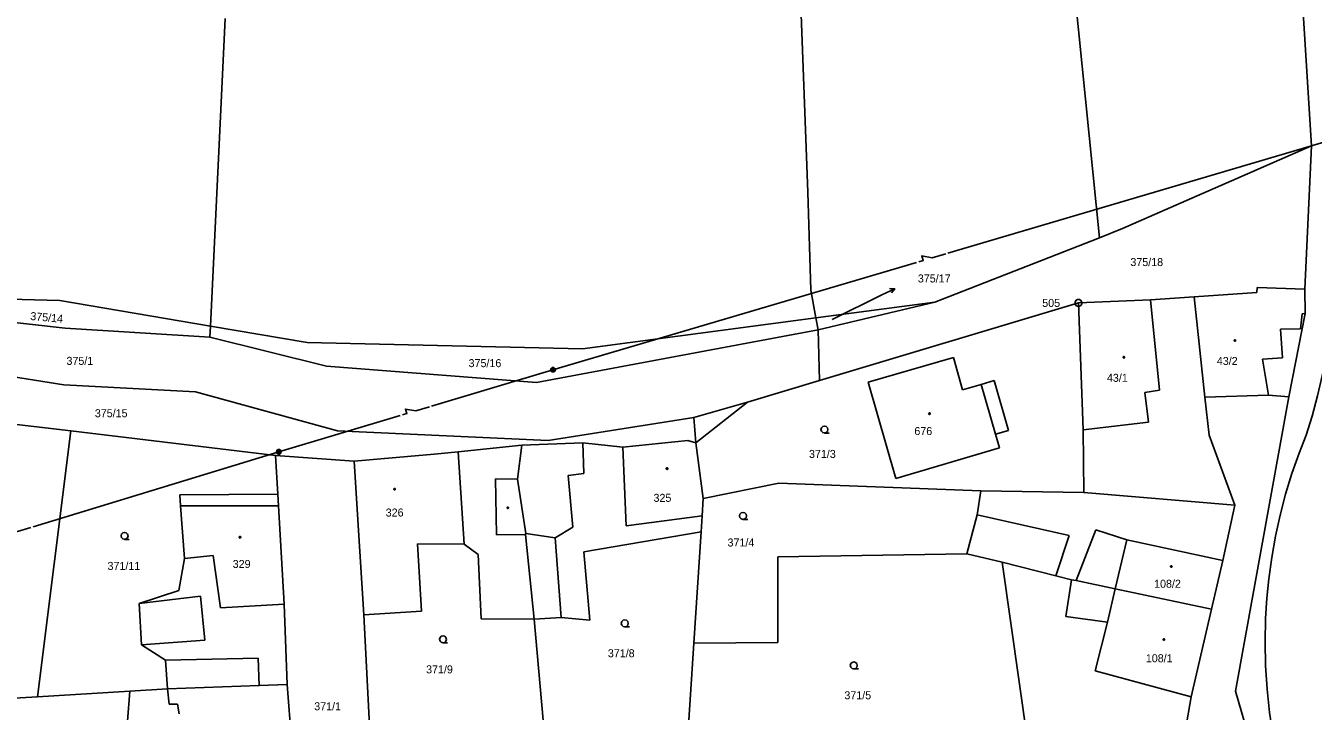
# Model space of a CAD drawing. Extents: x -757994 to -755874, y -1047691 to -1046119.
# Drawn here: x -757584.9 to -757448.1, y -1046913.8 to -1046841 of the extents above; entities that cross this region are included whole.
import ezdxf

# ---------------------------------------------------------------- set-up
doc = ezdxf.new("R2010")
doc.units = 0
doc.layers.add('katastrální mapa', color=7, linetype='Continuous')

msp = doc.modelspace()

# ---------------------------------------------------------------- linework, layer by layer
at = {"layer": 'katastrální mapa'}
for p, q in [((-757448.32, -1046853.75), (-757454.6, -1046754.14)), ((-757504.01, -1046800.91), (-757501.79, -1046858.7)), ((-757476.92, -1046802.81), (-757470.84, -1046863.52)), ((-757565.25, -1046872.91), (-757563.68, -1046840.26)), ((-757448.32, -1046853.75), (-757408.05, -1046841.78)), ((-757486.92, -1046865.15), (-757448.32, -1046853.75)), ((-757468.39, -1046862.56), (-757448.32, -1046853.75)), ((-757448.32, -1046853.75), (-757449.04, -1046868.97)), ((-757501.49, -1046869.09), (-757501.79, -1046858.7)), ((-757488.32, -1046870.35), (-757470.84, -1046863.52)), ((-757470.84, -1046863.52), (-757468.39, -1046862.56)), ((-757528.87, -1046877.54), (-757490.27, -1046866.14)), ((-757580.68, -1046873.11), (-757631.91, -1046867.41)), ((-757500.95, -1046872.02), (-757501.49, -1046869.09)), ((-757492.58, -1046868.93), (-757493.93, -1046869.59)), ((-757454.11, -1046869.33), (-757454.08, -1046868.81)), ((-757454.08, -1046868.81), (-757449.04, -1046868.97)), ((-757449.04, -1046868.97), (-757448.99, -1046871.58)), ((-757606.82, -1046869.48), (-757581.23, -1046870.2)), ((-757581.23, -1046870.2), (-757565.25, -1046872.91)), ((-757488.32, -1046870.35), (-757500.95, -1046872.02)), ((-757488.32, -1046870.35), (-757500.72, -1046873.3)), ((-757500.55, -1046878.68), (-757473.06, -1046870.44)), ((-757499.23, -1046872.2), (-757493.93, -1046869.59)), ((-757473.09, -1046870.44), (-757473.04, -1046870.44)), ((-757473.06, -1046870.44), (-757465.41, -1046870.1)), ((-757472.58, -1046883.93), (-757473.06, -1046870.44)), ((-757465.41, -1046870.1), (-757460.79, -1046869.79)), ((-757465.41, -1046870.1), (-757464.45, -1046879.69)), ((-757460.79, -1046869.79), (-757454.11, -1046869.33)), ((-757459.65, -1046880.44), (-757460.79, -1046869.79)), ((-757448.99, -1046871.58), (-757450.72, -1046880.42)), ((-757449.47, -1046873.21), (-757449.29, -1046871.59)), ((-757449.29, -1046871.59), (-757448.99, -1046871.58)), ((-757565.31, -1046874.08), (-757580.68, -1046873.11)), ((-757565.31, -1046874.08), (-757565.25, -1046872.91)), ((-757565.25, -1046872.91), (-757554.97, -1046874.65)), ((-757500.95, -1046872.02), (-757525.74, -1046875.3)), ((-757500.72, -1046873.3), (-757500.95, -1046872.02)), ((-757451.61, -1046873.22), (-757449.47, -1046873.21)), ((-757451.41, -1046876.26), (-757451.61, -1046873.22)), ((-757565.31, -1046874.08), (-757552.9, -1046877.15)), ((-757530.6, -1046878.9), (-757500.72, -1046873.3)), ((-757500.55, -1046878.68), (-757500.72, -1046873.3)), ((-757554.97, -1046874.65), (-757525.74, -1046875.3)), ((-757592.55, -1046877.25), (-757580.81, -1046879.14)), ((-757552.9, -1046877.15), (-757530.6, -1046878.9)), ((-757495.39, -1046878.84), (-757486.35, -1046876.25)), ((-757486.35, -1046876.25), (-757485.37, -1046879.66)), ((-757453.52, -1046876.4), (-757451.41, -1046876.26)), ((-757452.87, -1046880.22), (-757453.52, -1046876.4)), ((-757541.75, -1046881.4), (-757528.87, -1046877.54)), ((-757508.2, -1046880.97), (-757500.55, -1046878.68)), ((-757483.4, -1046879.09), (-757482.01, -1046878.69)), ((-757482.01, -1046878.69), (-757480.49, -1046883.98)), ((-757580.81, -1046879.14), (-757566.82, -1046879.87)), ((-757566.82, -1046879.87), (-757551.76, -1046884.04)), ((-757492.44, -1046889.08), (-757495.39, -1046878.84)), ((-757485.37, -1046879.66), (-757483.4, -1046879.09)), ((-757483.4, -1046879.09), (-757481.88, -1046884.38)), ((-757464.45, -1046879.69), (-757466.03, -1046879.96)), ((-757466.03, -1046879.96), (-757465.61, -1046883.11)), ((-757513.9, -1046882.61), (-757508.2, -1046880.97)), ((-757508.2, -1046880.97), (-757513.68, -1046885.3)), ((-757459.65, -1046880.44), (-757452.87, -1046880.22)), ((-757459.19, -1046884.47), (-757459.65, -1046880.44)), ((-757450.72, -1046880.42), (-757456.38, -1046911.66)), ((-757452.87, -1046880.22), (-757450.72, -1046880.42)), ((-757592.19, -1046882.58), (-757580.08, -1046884.04)), ((-757557.98, -1046886.26), (-757545.1, -1046882.4)), ((-757529.38, -1046885.05), (-757513.9, -1046882.61)), ((-757513.68, -1046885.3), (-757513.9, -1046882.61)), ((-757583.59, -1046912.25), (-757580.08, -1046884.04)), ((-757580.08, -1046884.04), (-757558.35, -1046886.65)), ((-757551.76, -1046884.04), (-757529.38, -1046885.05)), ((-757480.49, -1046883.98), (-757481.88, -1046884.38)), ((-757465.61, -1046883.11), (-757472.58, -1046883.93)), ((-757472.51, -1046890.58), (-757472.58, -1046883.93)), ((-757538.93, -1046886.24), (-757532.19, -1046885.54)), ((-757532.64, -1046889.17), (-757532.19, -1046885.54)), ((-757532.19, -1046885.54), (-757525.7, -1046885.3)), ((-757525.7, -1046885.3), (-757521.45, -1046885.75)), ((-757525.7, -1046885.3), (-757525.58, -1046888.55)), ((-757521.45, -1046885.75), (-757514.56, -1046885.05)), ((-757514.56, -1046885.05), (-757513.68, -1046885.3)), ((-757512.9, -1046891.21), (-757513.68, -1046885.3)), ((-757481.88, -1046884.38), (-757481.46, -1046885.82)), ((-757456.45, -1046891.91), (-757459.19, -1046884.47)), ((-757584.06, -1046894.21), (-757557.98, -1046886.26)), ((-757558.1, -1046890.76), (-757558.35, -1046886.65)), ((-757558.35, -1046886.65), (-757549.99, -1046887.23)), ((-757549.99, -1046887.23), (-757541.5, -1046886.51)), ((-757541.5, -1046886.51), (-757538.93, -1046886.24)), ((-757538.29, -1046896.07), (-757538.93, -1046886.24)), ((-757521.08, -1046894.1), (-757521.45, -1046885.75)), ((-757481.46, -1046885.82), (-757492.44, -1046889.08)), ((-757549.36, -1046896.84), (-757549.99, -1046887.23)), ((-757534.87, -1046895.08), (-757534.96, -1046889.11)), ((-757534.96, -1046889.11), (-757532.64, -1046889.17)), ((-757531.75, -1046894.92), (-757532.64, -1046889.17)), ((-757525.58, -1046888.55), (-757527.27, -1046888.78)), ((-757527.27, -1046888.78), (-757526.77, -1046894.24)), ((-757512.9, -1046891.21), (-757504.89, -1046889.58)), ((-757504.89, -1046889.58), (-757483.43, -1046890.38)), ((-757568.5, -1046890.8), (-757558.1, -1046890.76)), ((-757568.41, -1046892), (-757568.5, -1046890.8)), ((-757558.03, -1046891.98), (-757558.1, -1046890.76)), ((-757483.43, -1046890.38), (-757483.82, -1046892.95)), ((-757483.43, -1046890.38), (-757472.51, -1046890.58)), ((-757472.51, -1046890.58), (-757456.45, -1046891.91)), ((-757558.03, -1046891.98), (-757568.41, -1046892)), ((-757567.98, -1046897.57), (-757568.41, -1046892)), ((-757557.4, -1046902.41), (-757558.03, -1046891.98)), ((-757513.02, -1046893.06), (-757512.9, -1046891.21)), ((-757457.74, -1046897.79), (-757456.45, -1046891.91)), ((-757513.02, -1046893.06), (-757521.08, -1046894.1)), ((-757513.13, -1046894.73), (-757513.02, -1046893.06)), ((-757483.82, -1046892.95), (-757484.92, -1046897.09)), ((-757483.82, -1046892.95), (-757474.04, -1046895.14)), ((-757531.79, -1046895.03), (-757534.87, -1046895.08)), ((-757531.79, -1046895.03), (-757531.75, -1046894.92)), ((-757530.85, -1046904.01), (-757531.79, -1046895.03)), ((-757528.64, -1046895.39), (-757531.75, -1046894.92)), ((-757526.77, -1046894.24), (-757528.64, -1046895.39)), ((-757513.13, -1046894.73), (-757525.59, -1046896.87)), ((-757513.9, -1046906.58), (-757513.13, -1046894.73)), ((-757473.31, -1046899.91), (-757471.21, -1046894.54)), ((-757471.21, -1046894.54), (-757467.91, -1046895.6)), ((-757542.83, -1046903.17), (-757543.27, -1046896.03)), ((-757543.27, -1046896.03), (-757538.29, -1046896.07)), ((-757538.29, -1046896.07), (-757536.8, -1046897.15)), ((-757528.64, -1046895.39), (-757528, -1046903.84)), ((-757474.04, -1046895.14), (-757475.48, -1046899.42)), ((-757467.91, -1046895.6), (-757469.15, -1046900.79)), ((-757467.91, -1046895.6), (-757457.74, -1046897.79)), ((-757568.61, -1046900.98), (-757567.98, -1046897.57)), ((-757567.98, -1046897.57), (-757564.97, -1046897.25)), ((-757564.97, -1046897.25), (-757564.19, -1046902.82)), ((-757549.36, -1046896.84), (-757548.94, -1046903.57)), ((-757536.8, -1046897.15), (-757536.49, -1046903.99)), ((-757525.59, -1046896.87), (-757524.97, -1046904.12)), ((-757505, -1046897.4), (-757484.92, -1046897.09)), ((-757505, -1046906.5), (-757505, -1046897.4)), ((-757484.92, -1046897.09), (-757481.16, -1046897.98)), ((-757458.94, -1046902.94), (-757457.74, -1046897.79)), ((-757478.46, -1046916.96), (-757481.16, -1046897.98)), ((-757481.16, -1046897.98), (-757475.48, -1046899.42)), ((-757475.48, -1046899.42), (-757473.82, -1046899.84)), ((-757474.4, -1046903.73), (-757473.82, -1046899.84)), ((-757473.82, -1046899.84), (-757473.31, -1046899.91)), ((-757473.31, -1046899.91), (-757469.15, -1046900.79)), ((-757572.82, -1046902.37), (-757568.61, -1046900.98)), ((-757566.28, -1046901.57), (-757572.82, -1046902.37)), ((-757565.84, -1046906.26), (-757566.28, -1046901.57)), ((-757469.99, -1046904.33), (-757469.15, -1046900.79)), ((-757469.15, -1046900.79), (-757458.94, -1046902.94)), ((-757572.57, -1046906.74), (-757572.82, -1046902.37)), ((-757564.19, -1046902.82), (-757557.4, -1046902.41)), ((-757557.11, -1046910.95), (-757557.4, -1046902.41)), ((-757548.94, -1046903.57), (-757542.83, -1046903.17)), ((-757461.11, -1046912.25), (-757458.94, -1046902.94)), ((-757548.94, -1046903.57), (-757548.29, -1046916.7)), ((-757536.49, -1046903.99), (-757530.85, -1046904.01)), ((-757528, -1046903.84), (-757530.85, -1046904.01)), ((-757529.91, -1046914.73), (-757530.85, -1046904.01)), ((-757524.97, -1046904.12), (-757528, -1046903.84)), ((-757469.99, -1046904.33), (-757474.4, -1046903.73)), ((-757471.28, -1046909.51), (-757469.99, -1046904.33)), ((-757572.57, -1046906.74), (-757565.84, -1046906.26)), ((-757570.01, -1046908.36), (-757572.57, -1046906.74)), ((-757514.43, -1046914.75), (-757513.9, -1046906.58)), ((-757513.9, -1046906.58), (-757505, -1046906.5)), ((-757560.18, -1046908.16), (-757570.01, -1046908.36)), ((-757569.81, -1046911.41), (-757570.01, -1046908.36)), ((-757560.08, -1046911.05), (-757560.18, -1046908.16)), ((-757461.11, -1046912.25), (-757471.28, -1046909.51)), ((-757573.81, -1046911.65), (-757569.81, -1046911.41)), ((-757569.81, -1046911.41), (-757560.08, -1046911.05)), ((-757569.81, -1046911.41), (-757569.61, -1046913.05)), ((-757560.08, -1046911.05), (-757557.11, -1046910.95)), ((-757556.16, -1046922.73), (-757557.11, -1046910.95)), ((-757602.34, -1046913.4), (-757583.59, -1046912.25)), ((-757583.59, -1046912.25), (-757573.81, -1046911.65)), ((-757573.81, -1046911.65), (-757574.05, -1046914.86)), ((-757461.69, -1046915.73), (-757461.11, -1046912.25)), ((-757456.38, -1046911.66), (-757436.98, -1046978.47)), ((-757569.61, -1046913.05), (-757568.73, -1046913.04)), ((-757568.73, -1046913.04), (-757568.55, -1046914.08))]:
    msp.add_line(p, q, dxfattribs=at)
for points in [[(-757448.88, -1046884.49), (-757448.26, -1046882.45), (-757447.69, -1046880.32), (-757447.18, -1046878.17), (-757446.74, -1046876.01), (-757446.37, -1046873.91), (-757446.03, -1046871.63), (-757445.74, -1046869.09), (-757445.54, -1046866.55), (-757445.42, -1046863.99), (-757445.4, -1046861.69)], [(-757490.03, -1046866.07), (-757489.55, -1046865.93), (-757489.7, -1046865.45), (-757488.6, -1046865.65), (-757487.16, -1046865.22)], [(-757493.14, -1046868.92), (-757492.58, -1046868.93), (-757492.92, -1046869.37)], [(-757528.95, -1046877.3), (-757528.79, -1046877.3), (-757528.67, -1046877.39), (-757528.61, -1046877.54), (-757528.67, -1046877.68), (-757528.79, -1046877.77), (-757528.95, -1046877.77), (-757529.07, -1046877.68), (-757529.12, -1046877.54), (-757529.07, -1046877.39), (-757528.95, -1046877.3), (-757528.93, -1046877.32), (-757528.81, -1046877.32), (-757528.73, -1046877.36), (-757529.01, -1046877.36), (-757529.05, -1046877.4), (-757528.69, -1046877.4), (-757528.69, -1046877.44), (-757529.05, -1046877.44), (-757529.07, -1046877.48), (-757528.67, -1046877.48), (-757528.65, -1046877.52), (-757529.09, -1046877.52), (-757529.09, -1046877.56), (-757528.65, -1046877.56), (-757528.67, -1046877.6), (-757529.07, -1046877.6), (-757529.07, -1046877.64), (-757528.66, -1046877.64), (-757528.69, -1046877.68), (-757529.04, -1046877.68), (-757529.01, -1046877.72), (-757528.73, -1046877.72), (-757528.78, -1046877.76), (-757528.95, -1046877.76)], [(-757544.86, -1046882.33), (-757544.38, -1046882.19), (-757544.53, -1046881.71), (-757543.43, -1046881.9), (-757541.99, -1046881.47)], [(-757500.03, -1046884.25), (-757500.22, -1046884.2), (-757500.35, -1046884.07), (-757500.41, -1046883.88), (-757500.35, -1046883.7), (-757500.22, -1046883.56), (-757500.04, -1046883.51), (-757499.85, -1046883.56), (-757499.72, -1046883.7), (-757499.67, -1046883.89), (-757499.72, -1046884.08), (-757499.85, -1046884.21), (-757500.04, -1046884.26), (-757499.54, -1046884.26)], [(-757451.4, -1046920.95), (-757451.91, -1046918.86), (-757452.39, -1046916.4), (-757452.77, -1046913.93), (-757453.04, -1046911.44), (-757453.2, -1046908.94), (-757453.25, -1046906.44), (-757453.19, -1046903.94), (-757453.05, -1046901.79), (-757452.85, -1046899.75), (-757452.54, -1046897.48), (-757452.14, -1046895.22), (-757451.64, -1046892.98), (-757451.06, -1046890.76), (-757450.39, -1046888.56), (-757449.63, -1046886.39), (-757448.88, -1046884.49)], [(-757558.05, -1046886.02), (-757557.9, -1046886.02), (-757557.77, -1046886.11), (-757557.73, -1046886.26), (-757557.77, -1046886.4), (-757557.9, -1046886.49), (-757558.05, -1046886.49), (-757558.18, -1046886.4), (-757558.23, -1046886.26), (-757558.18, -1046886.11), (-757558.05, -1046886.02), (-757558.04, -1046886.04), (-757557.92, -1046886.04), (-757557.84, -1046886.08), (-757558.12, -1046886.08), (-757558.16, -1046886.12), (-757557.8, -1046886.12), (-757557.8, -1046886.16), (-757558.16, -1046886.16), (-757558.18, -1046886.2), (-757557.78, -1046886.2), (-757557.76, -1046886.24), (-757558.2, -1046886.24), (-757558.2, -1046886.28), (-757557.76, -1046886.28), (-757557.77, -1046886.32), (-757558.18, -1046886.32), (-757558.18, -1046886.36), (-757557.77, -1046886.36), (-757557.79, -1046886.4), (-757558.16, -1046886.4), (-757558.11, -1046886.44), (-757557.84, -1046886.44), (-757557.89, -1046886.48), (-757558.06, -1046886.48)], [(-757508.68, -1046893.42), (-757508.87, -1046893.37), (-757509.01, -1046893.24), (-757509.06, -1046893.05), (-757509.01, -1046892.87), (-757508.87, -1046892.73), (-757508.69, -1046892.68), (-757508.5, -1046892.73), (-757508.36, -1046892.87), (-757508.32, -1046893.06), (-757508.36, -1046893.25), (-757508.5, -1046893.38), (-757508.69, -1046893.43), (-757508.19, -1046893.43)], [(-757587.17, -1046895.16), (-757586.69, -1046895.02), (-757586.84, -1046894.54), (-757585.73, -1046894.72), (-757584.3, -1046894.29)], [(-757574.36, -1046895.54), (-757574.55, -1046895.49), (-757574.69, -1046895.36), (-757574.73, -1046895.17), (-757574.69, -1046894.99), (-757574.55, -1046894.85), (-757574.36, -1046894.8), (-757574.18, -1046894.85), (-757574.04, -1046894.99), (-757573.99, -1046895.18), (-757574.04, -1046895.37), (-757574.18, -1046895.5), (-757574.37, -1046895.55), (-757573.87, -1046895.55)], [(-757521.24, -1046904.83), (-757521.43, -1046904.78), (-757521.57, -1046904.65), (-757521.61, -1046904.46), (-757521.57, -1046904.27), (-757521.43, -1046904.14), (-757521.24, -1046904.09), (-757521.06, -1046904.14), (-757520.93, -1046904.27), (-757520.88, -1046904.47), (-757520.93, -1046904.66), (-757521.06, -1046904.79), (-757521.25, -1046904.84), (-757520.75, -1046904.84)], [(-757540.54, -1046906.52), (-757540.73, -1046906.47), (-757540.86, -1046906.34), (-757540.92, -1046906.15), (-757540.86, -1046905.97), (-757540.73, -1046905.83), (-757540.55, -1046905.78), (-757540.36, -1046905.83), (-757540.23, -1046905.97), (-757540.18, -1046906.16), (-757540.23, -1046906.35), (-757540.36, -1046906.48), (-757540.55, -1046906.53), (-757540.05, -1046906.53)], [(-757496.92, -1046909.29), (-757497.11, -1046909.24), (-757497.25, -1046909.11), (-757497.3, -1046908.92), (-757497.25, -1046908.74), (-757497.11, -1046908.6), (-757496.93, -1046908.55), (-757496.74, -1046908.6), (-757496.6, -1046908.74), (-757496.56, -1046908.93), (-757496.6, -1046909.12), (-757496.74, -1046909.25), (-757496.93, -1046909.3), (-757496.43, -1046909.3)]]:
    msp.add_lwpolyline(points, dxfattribs=at)
for points in [[(-757472.97, -1046870.08), (-757472.8, -1046870.17), (-757472.7, -1046870.35), (-757472.7, -1046870.54), (-757472.8, -1046870.71), (-757472.97, -1046870.8), (-757473.16, -1046870.8), (-757473.33, -1046870.71), (-757473.43, -1046870.54), (-757473.43, -1046870.35), (-757473.33, -1046870.17), (-757473.16, -1046870.08)], [(-757456.45, -1046874.35), (-757456.4, -1046874.36), (-757456.38, -1046874.4), (-757456.36, -1046874.43), (-757456.38, -1046874.48), (-757456.42, -1046874.51), (-757456.45, -1046874.52), (-757456.49, -1046874.5), (-757456.52, -1046874.47), (-757456.53, -1046874.43), (-757456.52, -1046874.39), (-757456.48, -1046874.35)], [(-757468.24, -1046876.14), (-757468.19, -1046876.15), (-757468.17, -1046876.19), (-757468.16, -1046876.22), (-757468.17, -1046876.26), (-757468.21, -1046876.3), (-757468.24, -1046876.3), (-757468.28, -1046876.29), (-757468.32, -1046876.26), (-757468.33, -1046876.22), (-757468.32, -1046876.18), (-757468.27, -1046876.14)], [(-757488.89, -1046882.12), (-757488.84, -1046882.12), (-757488.82, -1046882.17), (-757488.8, -1046882.2), (-757488.82, -1046882.24), (-757488.85, -1046882.28), (-757488.89, -1046882.28), (-757488.94, -1046882.27), (-757488.97, -1046882.24), (-757488.98, -1046882.2), (-757488.97, -1046882.16), (-757488.93, -1046882.12)], [(-757516.75, -1046887.95), (-757516.7, -1046887.96), (-757516.68, -1046888), (-757516.67, -1046888.03), (-757516.68, -1046888.08), (-757516.72, -1046888.11), (-757516.75, -1046888.12), (-757516.79, -1046888.1), (-757516.83, -1046888.07), (-757516.84, -1046888.03), (-757516.83, -1046887.99), (-757516.78, -1046887.95)], [(-757545.69, -1046890.14), (-757545.64, -1046890.15), (-757545.61, -1046890.19), (-757545.6, -1046890.22), (-757545.61, -1046890.26), (-757545.66, -1046890.3), (-757545.69, -1046890.3), (-757545.73, -1046890.29), (-757545.76, -1046890.26), (-757545.77, -1046890.22), (-757545.76, -1046890.18), (-757545.72, -1046890.14)], [(-757533.61, -1046892.12), (-757533.57, -1046892.19), (-757533.61, -1046892.26), (-757533.71, -1046892.26), (-757533.75, -1046892.19), (-757533.71, -1046892.12)], [(-757562.1, -1046895.23), (-757562.05, -1046895.24), (-757562.02, -1046895.28), (-757562.01, -1046895.31), (-757562.02, -1046895.36), (-757562.07, -1046895.39), (-757562.1, -1046895.4), (-757562.15, -1046895.38), (-757562.18, -1046895.35), (-757562.19, -1046895.31), (-757562.18, -1046895.27), (-757562.14, -1046895.23)], [(-757463.21, -1046898.35), (-757463.16, -1046898.36), (-757463.14, -1046898.4), (-757463.12, -1046898.43), (-757463.14, -1046898.48), (-757463.18, -1046898.51), (-757463.21, -1046898.52), (-757463.25, -1046898.5), (-757463.28, -1046898.47), (-757463.29, -1046898.43), (-757463.28, -1046898.39), (-757463.24, -1046898.35)], [(-757463.99, -1046906.1), (-757463.94, -1046906.11), (-757463.92, -1046906.15), (-757463.91, -1046906.18), (-757463.92, -1046906.23), (-757463.96, -1046906.26), (-757463.99, -1046906.27), (-757464.03, -1046906.25), (-757464.07, -1046906.22), (-757464.08, -1046906.18), (-757464.07, -1046906.14), (-757464.02, -1046906.1)]]:
    msp.add_lwpolyline(points, close=True, dxfattribs=at)

# ---------------------------------------------------------------- texts
for s, height, p in [('375/18', 0.85, (-757467.55, -1046866.53)), ('375/17', 0.85, (-757490.12, -1046868.27)), ('505', 0.85, (-757476.91, -1046870.87)), ('375/17', 0.05, (-757499.34, -1046872.2)), ('375/1', 0.85, (-757580.53, -1046877.02)), ('375/16', 0.85, (-757537.83, -1046877.26)), ('43/2', 0.85, (-757458.37, -1046877.03)), ('43/1', 0.85, (-757470.04, -1046878.82)), ('375/15', 0.85, (-757577.52, -1046882.58)), ('676', 0.85, (-757490.49, -1046884.47)), ('371/3', 0.85, (-757501.68, -1046886.9)), ('325', 0.85, (-757518.19, -1046891.56)), ('326', 0.85, (-757546.63, -1046893.12)), ('371/4', 0.85, (-757510.33, -1046896.3)), ('329', 0.85, (-757562.88, -1046898.58)), ('371/11', 0.85, (-757576.17, -1046898.79)), ('108/2', 0.85, (-757465.03, -1046900.68)), ('371/8', 0.85, (-757523.04, -1046908.06)), ('108/1', 0.85, (-757465.91, -1046908.59)), ('371/9', 0.85, (-757542.34, -1046909.77)), ('371/1', 0.85, (-757554.22, -1046913.69)), ('371/5', 0.85, (-757497.92, -1046912.52))]:
    msp.add_text(s, height=height, dxfattribs=at).set_placement(p)
msp.add_text('375/14', height=0.85, rotation=354.8901, dxfattribs=at).set_placement((-757584.4, -1046872.25))

doc.saveas('drawing.dxf')
